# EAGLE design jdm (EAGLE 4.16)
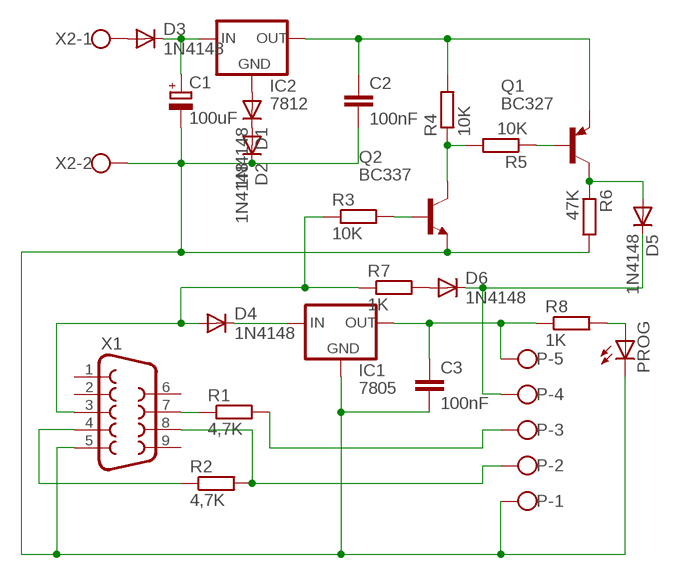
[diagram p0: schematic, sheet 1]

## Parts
C1  100uF  CPOL-EUE1.8-4  [E1,8-4]
C2  100nF  C-EU025-024X044  [C025-024X044]
C3  100nF  C-EU025-024X044  [C025-024X044]
D1  1N4148  [DO35-10]
D2  1N4148  [DO35-10]
D3  1N4148  [DO35-10]
D4  1N4148  [DO35-10]
D5  1N4148  [DO35-10]
D6  1N4148  [DO35-10]
IC1  7805  78LXX  [78LXX]
IC2  7812  78LXX  [78LXX]
P  W237-05P  [W237-5P]
PROG  LED5MM  [LED5MM]
Q1  BC327  [TO92]
Q2  BC337  [TO92]
R1  4,7K  R-EU_0204/7  [0204/7]
R2  4,7K  R-EU_0204/7  [0204/7]
R3  10K  R-EU_0204/7  [0204/7]
R4  10K  R-EU_0204/7  [0204/7]
R5  10K  R-EU_0204/7  [0204/7]
R6  47K  R-EU_0204/7  [0204/7]
R7  1K  R-EU_0204/7  [0204/7]
R8  1K  R-EU_0204/7  [0204/7]
X1  F09HP  [F09HP]
X2  W237-102  [W237-102]

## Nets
N$1: D5.A Q1.3(C) R6.1
N$2: D3.A X2.1
N$3: D1.C D2.A
N$4: R1.1 X1.7
N$5: D1.A IC2.GND
N$6: C1.+ D3.C IC2.IN
N$7: C1.- C2.2 C3.2 D2.C IC1.GND P.1 PROG.K(C) Q2.1(E) R6.2 X1.5 X2.2
N$8: C2.1 IC2.OUT Q1.1(E) R4.2
N$9: D6.A R7.2
N$10: D4.C IC1.IN
N$11: C3.1 IC1.OUT P.5 R8.1
N$12: P.3 R1.2
N$13: R2.1 X1.4
N$14: P.2 R2.2 X1.8
N$15: Q2.2(B) R3.2
N$16: Q2.3(C) R4.1 R5.2
N$17: Q1.2(B) R5.1
N$18: D5.C D6.C P.4
N$19: D4.A R3.1 R7.1 X1.3
N$20: PROG.A R8.2
Unconnected: X1.1 X1.2 X1.6 X1.9

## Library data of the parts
C1 = rcl:CPOL-EU: POLARIZED CAPACITOR, European symbol
C2 C3 = rcl:C-EU: CAPACITOR, European symbol
D1-D6 = diode:1N4148: DIODE
IC1 IC2 = v-reg:78LXX: VOLTAGE REGULATOR
P = con-wago-508:W237-05P: WAGO SREW CLAMP
PROG = led:LED: LED
Q1 = transistor-pnp:BC327: PNP Transistor
Q2 = transistor-npn:BC337*: NPN Transistor
R1-R8 = rcl:R-EU_: RESISTOR, European symbol
X1 = con-subd:F09: HARTING SUB-D
X2 = con-wago-500:W237-102: WAGO SCREW CLAMP

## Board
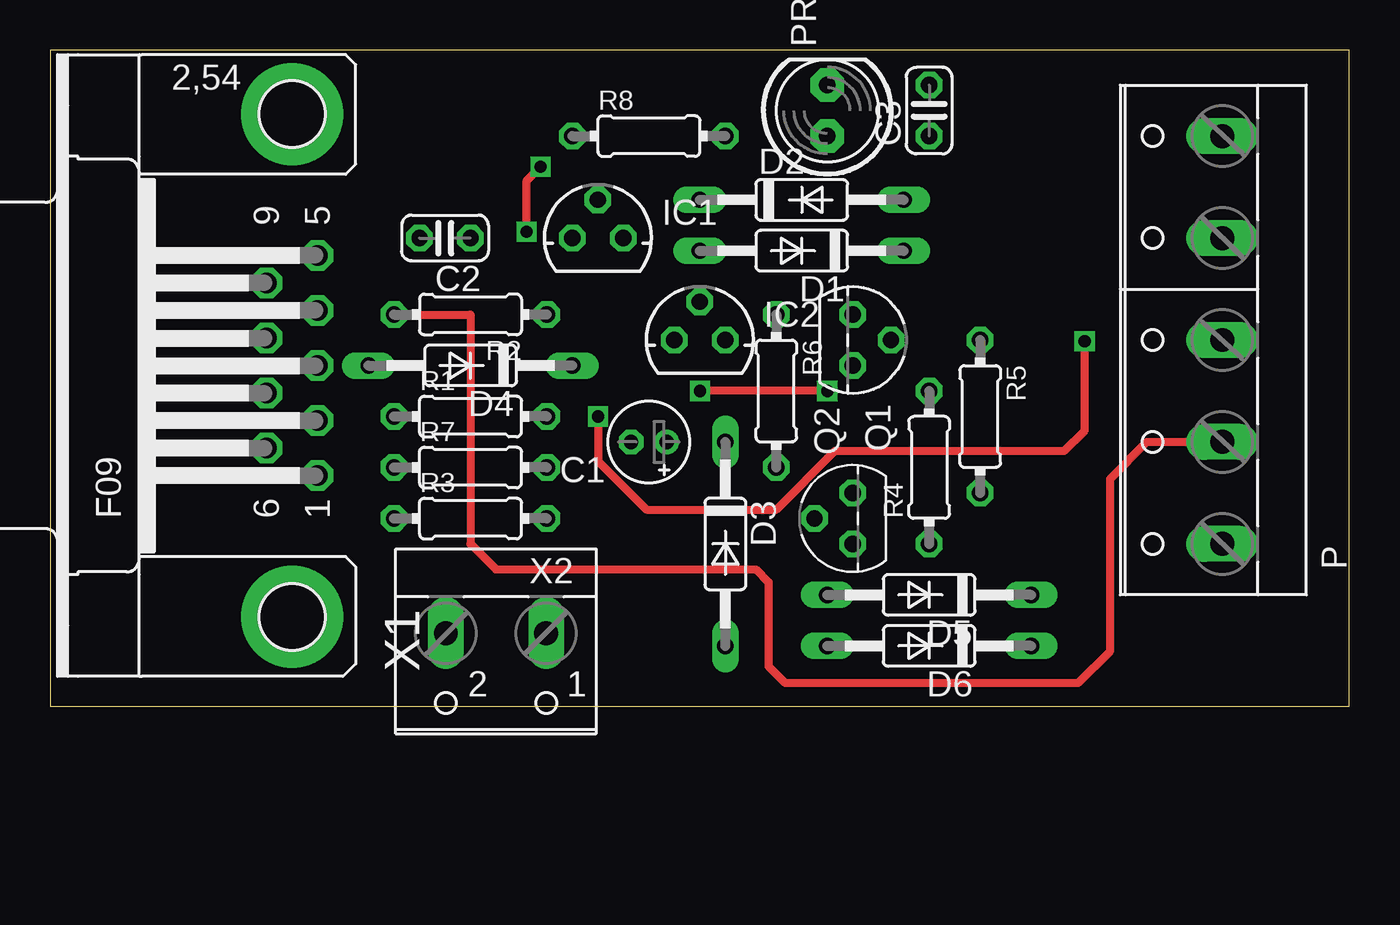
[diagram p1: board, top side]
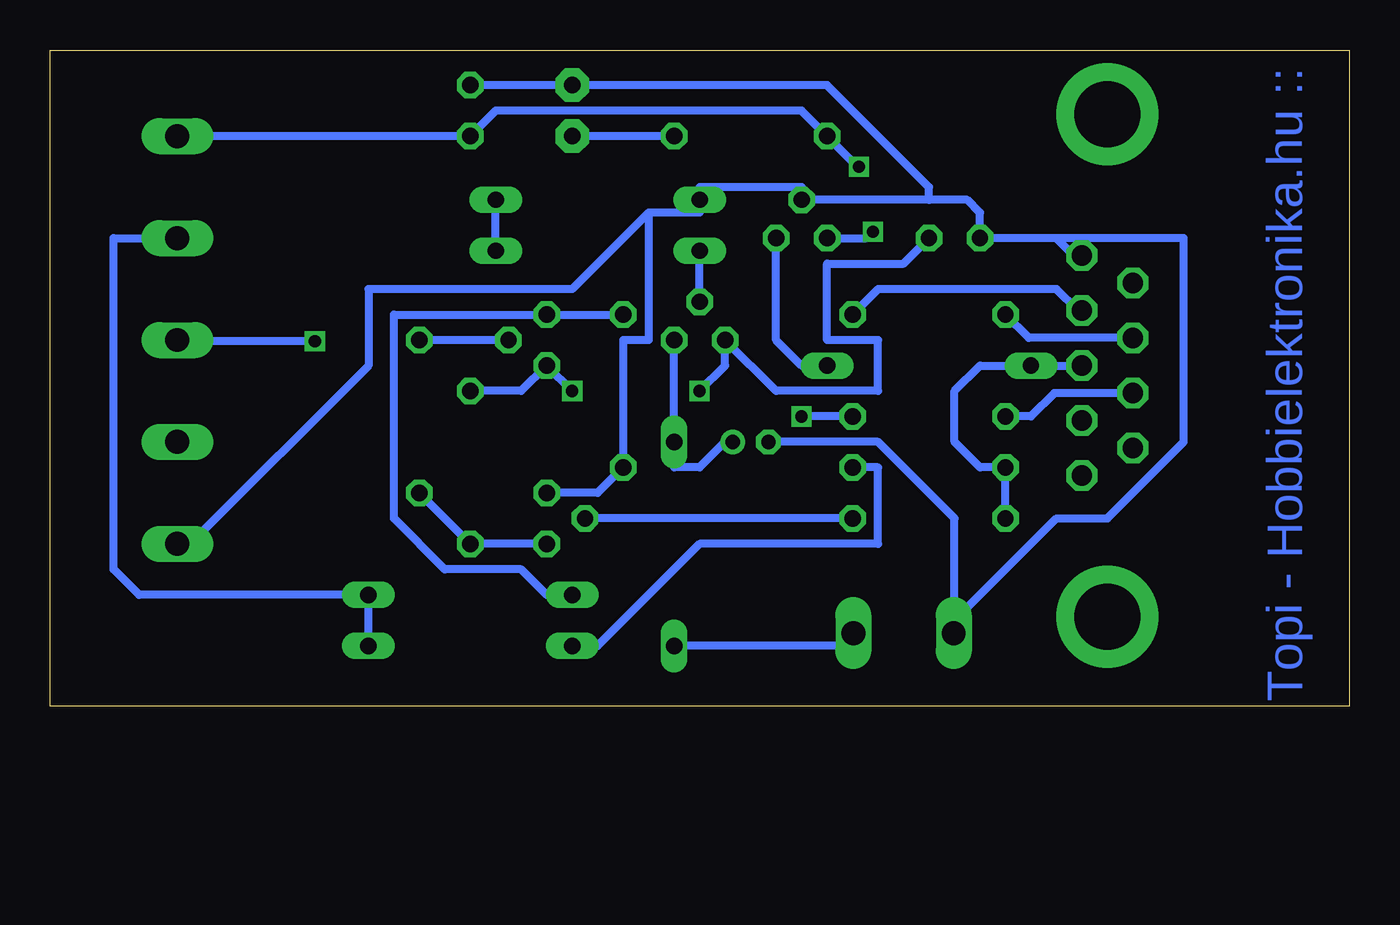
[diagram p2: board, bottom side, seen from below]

Size 64.75 x 32.69 mm. Coordinates in mm from the lower left corner, seen from the top.
Outline: 0,0 64.75,0 64.75,32.69 0,32.69 0,0
Copper layers (1*16): Top 0.035mm / dielectric 1.5mm / Bottom 0.035mm
Design rules "default": minimum track width 10mil, minimum drill 24mil, track to track 8mil, track to pad 8mil, pad to pad 8mil, via to via 8mil, smd to smd 8mil, copper to edge 40mil, drill to drill 8mil, minimum pad ring 10mil, minimum via ring 8mil, stop-mask expansion 4mil, vias tented up to drill 0mil, thermal gap 10mil

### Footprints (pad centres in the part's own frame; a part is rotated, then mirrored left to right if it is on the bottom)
E1,8-4 = drill 0.711 pad 1.168 round: + -0.889,0 | drill 0.711 pad 1.168 octagon: - 0.889,0
C025-024X044 = drill 0.813 octagon: 1 -1.27,0; 2 1.27,0
DO35-10 = drill 0.813 long: A 5.08,0; C -5.08,0
78LXX = drill 0.813 octagon: GND 0,1.905; IN 1.27,0; OUT -1.27,0
W237-5P = drill 1.194 long: 1 -10.16,-0.635; 2 -5.08,-0.635; 3 0,-0.635; 4 5.08,-0.635; 5 10.16,-0.635
LED5MM = drill 0.813 pad 1.676 octagon: A -1.27,0; K 1.27,0
TO92 = drill 0.813 octagon: 1 1.27,0; 2 0,1.905; 3 -1.27,0
0204/7 = drill 0.813 octagon: 1 -3.81,0; 2 3.81,0
F09HP = drill 1.016 octagon: 1 -5.486,-1.27; 2 -2.743,-1.27; 3 0,-1.27; 4 2.743,-1.27; 5 5.486,-1.27; 6 -4.115,1.27; 7 -1.372,1.27; 8 1.372,1.27; 9 4.115,1.27 | drill 3.302 pad 5.08 round: G1 -12.522,0; G2 12.522,0
W237-102 = drill 1.194 long: 1 -2.5,-1.27; 2 2.5,-1.27

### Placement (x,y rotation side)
C1  29.84,13.17 180 top
C2  19.68,23.33 180 top
C3  43.81,29.68 90 top
D1  37.46,22.69 180 top
D2  37.46,25.23 0 top
D3  33.65,8.09 270 top
D4  20.95,16.98 180 top
D5  43.81,5.55 180 top
D6  43.81,3.01 180 top
IC1  27.3,23.33 0 top
IC2  32.38,18.25 0 top
P  57.78,18.25 90 top
PROG  38.73,29.68 90 top
Q1  40,18.25 270 top
Q2  40,9.36 90 top
R1  20.95,14.44 0 top
R2  20.95,19.52 180 top
R3  20.95,9.36 0 top
R4  43.81,11.9 90 top
R5  46.35,14.44 270 top
R6  36.19,15.71 270 top
R7  20.95,11.9 0 top
R8  29.84,28.41 0 top
X1  12.06,16.98 90 top
X2  22.22,2.38 180 top

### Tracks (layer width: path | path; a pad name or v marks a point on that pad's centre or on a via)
N$1
  Bottom 0.406: D5.A 40,5.55 41.27,6.82 45.08,6.82 47.62,9.36 47.62,19.52 Q1.3 R6.1
N$2
  Bottom 0.406: D3.A 24.76,3.01 X2.1
N$3
  Bottom 0.406: D1.C D2.A
N$4
  Bottom 0.406: X1.7 14.7,15.61 15.87,14.44 R1.1
N$5
  Bottom 0.406: IC2.GND D1.A
N$6
  Bottom 0.406: C1.+ 31.11,13.17 32.38,11.9 33.65,11.9 D3.C IC2.IN
N$7
  Bottom 0.406: 20.95,25.23 19.04,25.23 18.41,24.6 C2.2 14.6,23.33 | 20.95,25.23 IC1.GND 27.3,25.87 32.38,25.87 D2.C 32.38,24.6 34.92,24.6 | X1.5 13.33,22.06 14.6,23.33 | 19.68,4.28 19.68,9.36 23.49,13.17 C1.- | C3.2 PROG.K 26.03,30.95 20.95,25.87 20.95,25.23 | Q2.1 37.46,10.63 R6.2 36.19,18.25 34.92,18.25 34.92,24.6 | 34.92,24.6 38.73,20.79 48.89,20.79 48.89,16.98 57.78,8.09 P.1 | 19.68,4.28 14.6,9.36 12.06,9.36 8.25,13.17 8.25,23.33 14.6,23.33 | X2.2 19.68,4.28
N$8  (via drill 0.6)
  Top 0.406: v38.73,15.71 v32.38,15.71
  Bottom 0.406: C2.1 22.22,22.06 26.03,22.06 26.03,18.25 23.49,18.25 23.49,15.71 28.57,15.71 IC2.OUT 31.11,16.98 v32.38,15.71 | R4.2 41.27,15.71 Q1.1 v38.73,15.71
N$9
  Bottom 0.406: R7.2 23.49,11.9 23.49,8.09 32.38,8.09 37.46,3.01 D6.A
N$10
  Bottom 0.406: D4.C 27.3,16.98 28.57,18.25 IC1.IN
N$11  (via drill 0.6)
  Top 0.406: v23.74,23.65 23.74,26.19 v24.44,26.89
  Bottom 0.406: P.5 C3.1 42.54,29.68 27.3,29.68 R8.1 24.51,26.89 v24.44,26.89 | IC1.OUT 24.06,23.33 v23.74,23.65
N$12  (via drill 0.6)
  Top 0.406: v27.3,14.44 27.3,12.22 29.71,9.8 36.19,9.8 39.11,12.73 50.54,12.73 51.56,13.74 v51.56,18.19
  Bottom 0.406: R1.2 v27.3,14.44 | v51.56,18.19 57.72,18.19 57.78,18.25 58.35,18.25 58.41,18.19 P.3
N$13
  Bottom 0.406: X1.4 13.53,19.72 14.6,20.79 23.49,20.79 R2.1
N$14
  Top 0.406: R2.2 20.95,19.52 20.95,8.09 22.22,6.82 35.17,6.82 35.81,6.19 35.81,1.99 36.64,1.17 51.24,1.17 52.83,2.76 52.83,11.33 54.67,13.17 P.2 58.48,13.11
  Bottom 0.406: X1.8 15.97,18.35 R2.2
N$15
  Bottom 0.406: R3.2 Q2.2
N$16
  Bottom 0.406: Q2.3 R4.1 R5.2
N$17
  Bottom 0.406: Q1.2 R5.1
N$18
  Bottom 0.406: D6.C D5.C 60.32,5.55 61.59,6.82 61.59,23.33 P.4
N$19
  Bottom 0.406: X1.3 D4.A 18.41,16.98 19.68,15.71 19.68,13.17 18.41,11.9 R7.1 R3.1
N$20
  Bottom 0.406: R8.2 PROG.A

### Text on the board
Bottom: Topi - Hobbielektronika.hu ::
